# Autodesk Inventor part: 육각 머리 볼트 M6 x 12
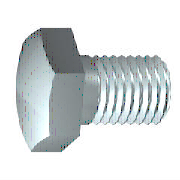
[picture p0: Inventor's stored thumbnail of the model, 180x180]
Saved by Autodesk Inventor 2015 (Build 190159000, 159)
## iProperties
IsCustomPart: 1
Created: 2012-02
Part Number: 육각 머리 볼트 M6 x 12
Material: 강철, 연강
Description: 6각 머리 나사
Document SubType Name: Modeling
Standard: ISO 4017
Designer: mdu-01
Standard Revision: Third edition 1999-08-15
Standards Organization: ISO
Language: ko-KR
Size Designation: M6 x 12
Categories: <MemberInstance><Categories><Category DisplayName="조임쇠" InternalName="e4da775c-781d-43d5-af7c-5136215cf5a6" Mnemonic="FSTN"><Category DisplayName="볼트" InternalN
Density: 7.75 g/cm^3
Appearance: 강철
Author: mdu-01
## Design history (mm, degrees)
sketch "스케치1"
  geometry: L1 (0, 4.44)-(0, 3); L2 (3, 3)-(12, 3); L3 (12, 3)-(12, 0); L4 (12, 0)-(-0.5, 0); L5 (-3, 0)-(14.5, 0) reference; L6 (-0.5, 0)-(-0.5, 4.44); L7 (-0.5, 4.44)-(0, 4.44); L8 (3, 3)-(2.386, 3); L9 (2.386, 3)-(0, 3); L10 (0, -0.888)-(0, 5.328) reference
  constraints: 16 end point, 2 collinear, 2 perpendicular, 1 parallel
  dimensions: "d0" = 12 distance between parallel lines of L3 L1 (= NLG); "d1" = 9 distance from line of L2.start L3 (= GEL); "d2" = 6 diameter of L2 L4 (= GD); "d9" = 0.5001 distance between parallel lines of L6 L1 (computed from SD); "d10" = 8.88 diameter of L7 L4 (= SD2); "d13" = 0.61355 distance of L2.start L8.end (computed from GAL); "d14" = 6 diameter of L9 L4 (= BDM)
revolve "본체" sketch "스케치1" stored, may be unused: angle "d12" = 90 deg
sketch "스케치2"
  geometry: L1 (0, 5.774)-(5, 2.887); L2 (5, 2.887)-(5, -2.887); L3 (5, -2.887)-(0, -5.774); L4 (0, -5.774)-(-5, -2.887); L5 (-5, -2.887)-(-5, 2.887); L6 (-5, 2.887)-(0, 5.774); 2 further points
  constraints: 12 end point, 1 coincident, 1 vertical, 11 other
  dimensions: "d11" = 10 distance between parallel lines of L5 L2 (= SW)
extrude "머리" join sketch "스케치2" distance "d3" = 3.5 (= KOH - SD); taper "d4" = 0 deg
sketch "스케치4"
  geometry: L1 (-4, 5)-(-4, 5.774); L2 (-4, 5.774)-(-3.554, 5.774); L3 (-3.554, 5.774)-(-4, 5); L4 (-4.7, 0)-(0.2, 0) reference; L5 (-0.5, 5.774)-(-4, 5.774) reference; L6 (-4, 2.887)-(-4, 5.774) reference
  constraints: 6 end point, 2 collinear, 1 perpendicular, 1 vertical
  dimensions: "d5" = 30 deg angle of L3 L1 (= ANG1); "d19" = 10 diameter of L1.start L4 (= SW0)
revolve "모따기1" sketch "스케치4" stored, may be unused: angle "d21" = 90 deg
workplane "Work Plane1"
body "Solid1"
feature "스레드" dims "d15" = 9 (= GEL), "d16" = 0
chamfer "모따기2" distance "d6" = 0.61345 (= -0.5 x SPD + 0.5 x GD); stored, may be unused: second distance "d7" = 0.61355 (computed from GUL), angle "d55" = 45 deg
other parameters: "NLG" = 12 [user parameter; used in 1 equation term], "GD" = 6 (= NND) [user parameter; used in 2 equation terms], "BDM" = 6 (= NND) [user parameter; used in 1 equation term], "KOH" = 4 [user parameter; used in 1 equation term], "GEL" = 9 [user parameter; used in 2 equation terms], "SW" = 10 [user parameter; used in 2 equation terms], "SW0" = 10 (= SW) [user parameter; used in 1 equation term], "SPD" = 4.7731 (= NND - 1.2269 x PTC) [user parameter; used in 1 equation term], "SD2" = 8.88 [user parameter; used in 2 equation terms], "SD" = 0.5 [user parameter; used in 2 equation terms], "ANG1" = 30 deg [user parameter; used in 1 equation term], "GAL" = 0.61345 (= 0.61345 x PTC) [user parameter; used in 1 equation term], "GUL" = 0.61345 (= 0.61345 x PTC) [user parameter; used in 1 equation term], "d8" = 0, "RR" = 0.25 [user parameter], "d57" = 0, "d58" = 0, "GD1" = 4.7731 (= THREADDIA - 1.2269 x PTC) [user parameter], "THREADDIA" = 6 [user parameter; used in 1 equation term], "SDH" = 8.88 (= SD2) [user parameter], "SDHG" = 3 [user parameter], "TOA" = 30 deg [user parameter], "PTC" = 1 [user parameter; used in 5 equation terms], "NND" = 6 [user parameter; used in 3 equation terms], "E0" = 11.55 [user parameter]
